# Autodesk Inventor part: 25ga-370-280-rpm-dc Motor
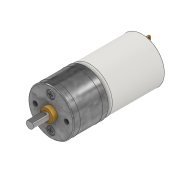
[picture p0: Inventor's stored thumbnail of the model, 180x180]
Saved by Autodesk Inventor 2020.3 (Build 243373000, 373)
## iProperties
Created: 2021-05
Part Number: 25ga-370-280-rpm-dc Motor
Material: Generic
Document SubType Name: Modeling
Designer: Suriyan.S
Density: 1 g/cm^3
Appearance: Titanium - Polished
Author: Suriyan.S
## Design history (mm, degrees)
sketch "Sketch1"
  geometry: C1 r 12.2 at (0, 0); 1 further point
  constraints: 1 centre point, 1 coincident
  dimensions: "d0" = 24.4 diameter of C1
extrude "Extrusion1" new body sketch "Sketch1" distance "d1" = 30.8; taper "d2" = 0 deg
fillet "Fillet1" dims "d3" = 2
sketch "Sketch2"
  geometry: L1 (7.5, -26.8)-(9.5, -26.8); L2 (9.5, -26.8)-(9.5, -34.8); L3 (9.5, -34.8)-(7.5, -34.8); L4 (7.5, -34.8)-(7.5, -26.8); L5 (-12.2, -30.8)-(12.2, -30.8) reference; L6 (7.5, -26.8)-(9.5, -34.8); L7 (9.5, -26.8)-(7.5, -34.8); L8 (-9.5, -26.8)-(-7.5, -26.8); L9 (-7.5, -26.8)-(-7.5, -34.8); L10 (-7.5, -34.8)-(-9.5, -34.8); L11 (-9.5, -34.8)-(-9.5, -26.8); L12 (-9.5, -26.8)-(-7.5, -34.8); L13 (-7.5, -26.8)-(-9.5, -34.8); L14 (0, 0)-(0, -39.684); L15 (9.5, -30.8)-(7.5, -30.8); L16 (-7.5, -30.8)-(-9.5, -30.8); C1 r 0.75 at (8.5, -33.3); C2 r 0.75 at (-8.5, -33.3); 4 further points
  constraints: 30 end point, 10 midpoint, 5 point on line, 4 parallel, 2 centre point, 2 horizontal, 2 perpendicular, 2 vertical alignment, 1 equal radius, 1 horizontal alignment, 1 vertical
  dimensions: "d4" = 2 distance of L9.end L10.end; "d5" = 2 distance of L2.end L3.end (= d4); "d6" = 8 distance of L1.end L2.end; "d7" = 15 distance between parallel lines of L9 L4; "d8" = 7.5 distance between parallel lines of L4 L14 (= 0.5 x d7); "d9" = 1.5 distance from line of C1.centre L3; "d10" = 1.5 diameter of C1
extrude "Extrusion2" new body sketch "Sketch2" stored distance "d11" = 1; taper "d12" = 0 deg
chamfer "Chamfer1" distance "d14" = 0.3; stored, may be unused: second distance "d15" = 2, angle "d16" = 45 deg
fillet "Fillet3" dims "d17" = 0.3
sketch "Sketch3"
  geometry: C1 r 12.2 at (0, 0) reference; C2 r 3.25 at (0, 0)
  constraints: 1 centre point, 1 coincident
  dimensions: "d18" = 6.5 diameter of C2
extrude "Extrusion3" new body sketch "Sketch3" distance "d19" = 2; taper "d20" = 0 deg
fillet "Fillet4" dims "d21" = 0.5
sketch "Sketch4"
  geometry: C1 r 3.25 at (0, 0) reference; C2 r 12.5 at (0, 0)
  constraints: 1 centre point, 1 coincident
  dimensions: "d22" = 25 diameter of C2
extrude "Extrusion4" new body sketch "Sketch4" distance "d23" = 19.2; taper "d24" = 0 deg
fillet "Fillet5" dims "d25" = 0.5
sketch "Sketch5"
  geometry: C1 r 3.25 at (0, 0) reference; C2 r 3.5 at (0, 0)
  constraints: 1 centre point, 1 coincident
  dimensions: "d26" = 7 diameter of C2
extrude "Extrusion5" new body sketch "Sketch5" distance "d27" = 2.5; taper "d28" = 0 deg
sketch "Sketch6"
  geometry: C1 r 3.25 at (0, 0) reference; C2 r 2 at (0, 0)
  constraints: 1 centre point, 1 coincident
  dimensions: "d29" = 4 diameter of C2
extrude "Extrusion6" new body sketch "Sketch6" distance "d30" = 9; taper "d31" = 0 deg
sketch "Sketch7"
  geometry: L1 (-2.5, 1.5)-(2.5, 1.5); L2 (2.5, 1.5)-(2.5, -1.5); L3 (2.5, -1.5)-(-2.5, -1.5); L4 (-2.5, -1.5)-(-2.5, 1.5); L5 (-2.5, 1.5)-(2.5, -1.5); L6 (2.5, 1.5)-(-2.5, -1.5); C1 r 2 at (0, 0) reference; 2 further points
  constraints: 12 end point, 2 midpoint, 2 parallel, 1 horizontal, 1 perpendicular
  dimensions: "d32" = 1.5 distance from line of C1.centre L1; "d33" = 5 distance of L2.end L3.end
extrude "Extrusion7" cut sketch "Sketch7" distance "d34" = 8; taper "d35" = 0 deg
sketch "Sketch8"
  geometry: L1 (12.75, 15.71)-(12.25, 15.71); L2 (12.25, 15.71)-(12.25, 15.69); L3 (12.25, 15.69)-(12.75, 15.69); L4 (12.75, 15.69)-(12.75, 15.71); L5 (12.5, 0.5)-(12.5, 18.7) reference; L6 (12.75, 15.71)-(12.25, 15.69); L7 (12.25, 15.71)-(12.75, 15.69); L8 (12.75, 3.49)-(12.25, 3.49); L9 (12.25, 3.49)-(12.25, 3.51); L10 (12.25, 3.51)-(12.75, 3.51); L11 (12.75, 3.51)-(12.75, 3.49); L12 (12.75, 3.49)-(12.25, 3.51); L13 (12.25, 3.49)-(12.75, 3.51); L14 (-12, 19.2)-(12, 19.2) reference; L15 (12, 0)-(-12, 0) reference; L16 (0, -3.84)-(0, 23.04) reference; 3 further points
  constraints: 24 end point, 4 midpoint, 4 parallel, 3 point on line, 2 horizontal, 2 perpendicular, 1 collinear
  dimensions: "d36" = 0.02 distance of L3.end L1.start; "d37" = 0.5 distance of L2.end L3.end; "d38" = 3.5 distance from line of L14 point (12.5, 15.7) (= d39); "d39" = 3.5 distance from line of L15 point (12.5, 3.5)
revolve "Revolution1" sketch "Sketch8" stored, may be unused: angle "d40" = 90 deg
fillet "Fillet6" dims "d41" = 0.01
fillet "Fillet7" dims "d42" = 0.01
sketch "Sketch9"
  geometry: 3 further points
  constraints: 2 vertical alignment
  dimensions: "d50" = 17 distance of point (0, -8.5) point (0, 8.5); "d51" = 8.5 distance of point (0, -8.5) point (0, 0) (= 0.5 x d50)
hole "Hole1" sketch "Sketch9" at (0, 8.5), (0, -8.5) diameter "d43" = 2.4; stored, may be unused: countersink angle "d47" = 90 deg, drill point angle "d49" = 118 deg; dims "d44" = 6, "d45" = 4.4, "d46" = 2.3, "d48" = 8
sketch "Sketch10"
  geometry: C1 r 3.25 at (0, 0) reference; A1 r 8.5 centre (0, 0) between (-8.5, 0) and (8.5, 0); 1 further point
  constraints: 2 horizontal alignment, 2 point on circle, 1 centre point, 1 coincident
  dimensions: "d59" = 17 diameter of A1
hole "Hole2" sketch "Sketch10" at (8.5, 0), (-8.5, 0) diameter "d52" = 2.459; stored, may be unused: countersink angle "d56" = 90 deg, drill point angle "d58" = 118 deg; dims "d53" = 6, "d54" = 4.4, "d55" = 2.3, "d57" = 8.8
sketch "Sketch11"
  geometry: C1 r 1.2 at (0, 0) reference; C2 r 2 at (0, 0); 1 further point
  constraints: 1 centre point
  dimensions: "d60" = 4 diameter of C2
extrude "Extrusion8" join sketch "Sketch11" distance "d61" = 2.5; taper "d62" = 0 deg
fillet "Fillet8" dims "d63" = 1
sketch "Sketch12"
  geometry: L1 (-1.25, 0.25)-(1.25, 0.25); L2 (1.25, 0.25)-(1.25, -0.25); L3 (1.25, -0.25)-(-1.25, -0.25); L4 (-1.25, -0.25)-(-1.25, 0.25); L5 (-1.25, 0.25)-(1.25, -0.25); L6 (1.25, 0.25)-(-1.25, -0.25); L7 (-0.25, 1.25)-(0.25, 1.25); L8 (0.25, 1.25)-(0.25, -1.25); L9 (0.25, -1.25)-(-0.25, -1.25); L10 (-0.25, -1.25)-(-0.25, 1.25); L11 (-0.25, 1.25)-(0.25, -1.25); L12 (0.25, 1.25)-(-0.25, -1.25); C1 r 1 at (0, 0) reference; 5 further points
  constraints: 24 end point, 4 midpoint, 4 parallel, 3 perpendicular, 2 horizontal
  dimensions: "d64" = 2.5 distance of L7.end L8.end; "d65" = 0.5 distance of L7.start L7.end; "d66" = 0.5 distance of L1.end L2.end
extrude "Extrusion9" cut sketch "Sketch12" distance "d67" = 0.5; taper "d68" = 0 deg
pattern_circular "Circular Pattern1" dims angle "d70" = 360 deg
fillet "Fillet9" dims "d72" = 0.5
body "Solid1"
body "Solid2"
body "Solid3"
body "Solid4"
body "Solid5"
body "Solid6"
